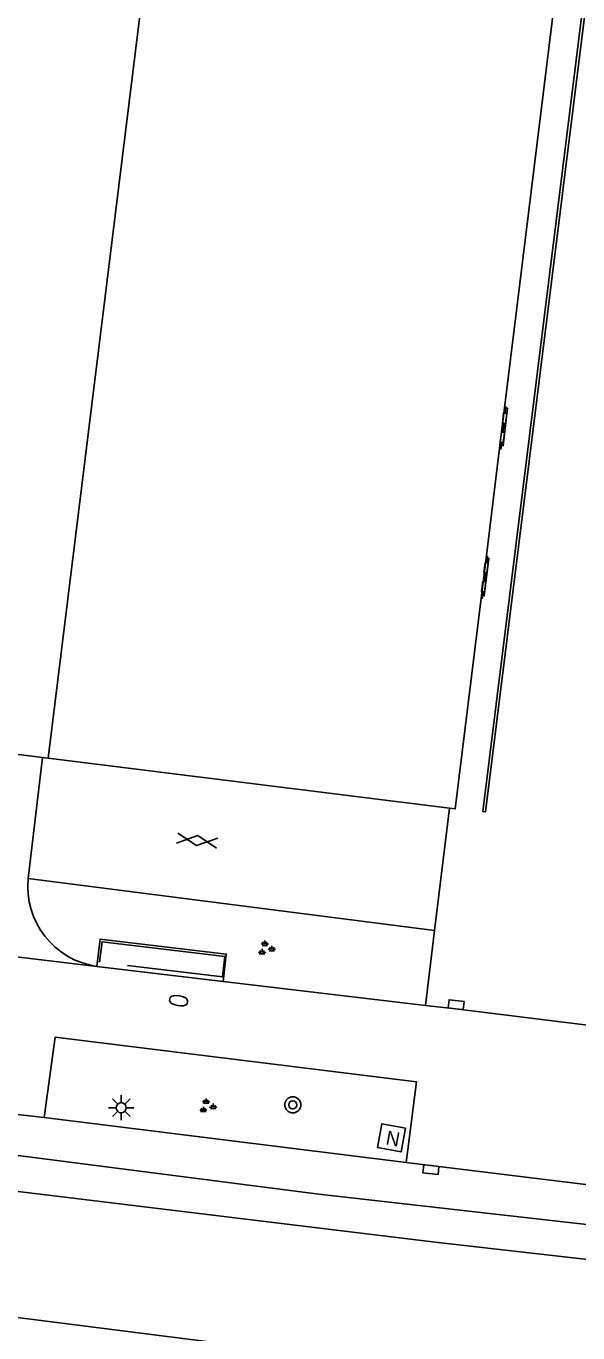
# Model space of a CAD drawing. Extents: x 131000 to 133014, y 396499 to 399001.
# Drawn here: x 131552 to 131579.4, y 397023 to 397087.7 of the extents above; entities that cross this region are included whole.
import ezdxf

# ---------------------------------------------------------------- set-up
doc = ezdxf.new("R2010")
doc.units = 0
for name, color, linetype in [('gg-afsc-hekwerk', 7, 'Continuous'), ('gg-bbg-hoofdgebouw', 7, 'Continuous'), ('gg-knt-verharding', 7, 'Continuous'), ('gg-knt-verharding nz', 7, 'Continuous'), ('gt-grn-afwateringsgoot', 7, 'Continuous'), ('gt-symb-afwateringsgoot', 7, 'Continuous'), ('gt-symb-boom', 7, 'Continuous'), ('gt-symb-brandkraan', 7, 'Continuous'), ('gt-symb-gesloten verharding', 7, 'Continuous'), ('gt-symb-groenvak', 7, 'Continuous'), ('gt-symb-kolk', 7, 'Continuous'), ('gt-symb-lichtmast', 7, 'Continuous'), ('gt-symb-nortonput', 7, 'Continuous')]:
    doc.layers.add(name, color=color, linetype=linetype)

# ---------------------------------------------------------------- blocks, each defined once
blk = doc.blocks.new('gt0-GESVH1')
at = {"layer": 'gt-symb-gesloten verharding'}
for p, q in [((-0.992, -0.261), (0.008, 0.239)), ((0.008, -0.261), (-0.992, 0.239)), ((0.008, 0.239), (1.008, -0.261)), ((1.008, 0.239), (0.008, -0.261))]:
    blk.add_line(p, q, dxfattribs=at)
blk = doc.blocks.new('gt0-BR')
at = {"layer": 'gt-symb-brandkraan'}
for centre, radius, start, end in [((-0.244, 0), 0.206, 107.56694, 252.43307), ((0.599, -2.664), 3, 106.89205, 107.56694), ((0, -0.691), 0.938, 73.10799, 106.89205), ((-0.599, -2.664), 3, 72.43309, 73.10799), ((0.244, 0), 0.206, 287.56695, 72.43309), ((0.599, 2.664), 3, 252.43307, 253.10797), ((0, 0.691), 0.938, 253.10797, 286.89206), ((-0.599, 2.664), 3, 286.89206, 287.56695)]:
    blk.add_arc(centre, radius, start, end, dxfattribs=at)
blk = doc.blocks.new('gt0-GRVAK')
at = {"layer": 'gt-symb-groenvak'}
for p, q in [((-0.11, 0.189), (-0.228, 0.24)), ((-0.182, 0.153), (0.088, 0.153)), ((-0.091, 0.211), (-0.156, 0.322)), ((-0.047, 0.214), (-0.047, 0.393)), ((-0.004, 0.211), (0.061, 0.322)), ((0.015, 0.189), (0.133, 0.24)), ((0.262, -0.052), (0.197, 0.059)), ((0.305, -0.049), (0.305, 0.13)), ((0.349, -0.052), (0.414, 0.059)), ((-0.245, -0.228), (-0.363, -0.177)), ((-0.318, -0.264), (-0.047, -0.264)), ((-0.226, -0.206), (-0.291, -0.095)), ((-0.183, -0.203), (-0.183, -0.024)), ((-0.139, -0.206), (-0.074, -0.095)), ((-0.12, -0.228), (-0.002, -0.177)), ((0.243, -0.074), (0.125, -0.023)), ((0.17, -0.11), (0.441, -0.11)), ((0.368, -0.074), (0.486, -0.023))]:
    blk.add_line(p, q, dxfattribs=at)
blk = doc.blocks.new('gt0-LMAST')
at = {"layer": 'gt-symb-lichtmast'}
for p, q in [((-0.182, 0.173), (-0.447, 0.438)), ((-0.005, 0.246), (-0.005, 0.621)), ((0.172, 0.173), (0.437, 0.438)), ((-0.255, -0.004), (-0.63, -0.004)), ((-0.182, -0.181), (-0.447, -0.446)), ((-0.005, -0.254), (-0.005, -0.629)), ((0.437, -0.446), (0.172, -0.181)), ((0.245, -0.004), (0.62, -0.004))]:
    blk.add_line(p, q, dxfattribs=at)
blk.add_circle((-0.005, -0.004), 0.25, dxfattribs=at)
blk = doc.blocks.new('gt0-BOOM')
at = {"layer": 'gt-symb-boom'}
for radius in [0.4, 0.2]:
    blk.add_circle((0, 0), radius, dxfattribs=at)
blk = doc.blocks.new('gt0-NPUT')
at = {"layer": 'gt-symb-nortonput'}
blk.add_lwpolyline([(-0.566, -0.608), (-0.566, 0.592), (0.634, 0.592), (0.634, -0.608)], close=True, dxfattribs=at)
blk.add_text('N', height=0.7, dxfattribs=at).set_placement((-0.221, -0.381))
blk = doc.blocks.new('gt0-AFWGT_1')
at = {"layer": 'gt-symb-afwateringsgoot'}
for p, q in [((-1.076, 0), (-0.726, 0)), ((-0.225, 0), (0.225, 0)), ((0.725, 0), (1.075, 0))]:
    blk.add_line(p, q, dxfattribs=at)
for points in [[(-0.726, 0.075), (-0.225, 0.075), (-0.225, -0.075), (-0.726, -0.075)], [(0.225, 0.075), (0.725, 0.075), (0.725, -0.075), (0.225, -0.075)]]:
    blk.add_lwpolyline(points, close=True, dxfattribs=at)
blk = doc.blocks.new('gt0-KOLK')
at = {"layer": 'gt-symb-kolk'}
blk.add_lwpolyline([(0, 0), (0.375, 0), (0.375, 0.4), (-0.375, 0.4), (-0.375, 0), (0, 0)], dxfattribs=at)

msp = doc.modelspace()

# ---------------------------------------------------------------- linework, layer by layer
at = {"layer": 'gg-afsc-hekwerk'}
msp.add_lwpolyline([(131555.696, 397041.331), (131555.816, 397042.343), (131561.914, 397041.62), (131561.793, 397040.607), (131557.076, 397041.167)], dxfattribs=at)
at = {"layer": 'gg-bbg-hoofdgebouw'}
for p, q in [((131561.421, 397118.541), (131553.14, 397051.44)), ((131575.788, 397068.814), (131578.302, 397089.226)), ((131575.558, 397066.948), (131575.788, 397068.814)), ((131574.871, 397061.367), (131575.558, 397066.948)), ((131574.641, 397059.505), (131574.871, 397061.367)), ((131553.14, 397051.44), (131573.05, 397048.976))]:
    msp.add_line(p, q, dxfattribs=at)
msp.add_lwpolyline([(131573.05, 397048.976), (131573.34, 397048.94), (131574.641, 397059.505)], dxfattribs=at)
at = {"layer": 'gg-knt-verharding'}
for p, q in [((131550.072, 397051.834), (131552.857, 397051.477)), ((131552.155, 397045.488), (131552.857, 397051.477)), ((131552.857, 397051.477), (131553.14, 397051.44)), ((131572.311, 397042.903), (131573.05, 397048.976)), ((131572.311, 397042.903), (131552.155, 397045.488)), ((131571.859, 397039.191), (131572.311, 397042.903)), ((131548.89, 397041.924), (131555.561, 397041.125)), ((131571.859, 397039.191), (131561.817, 397040.383)), ((131543.649, 397034.705), (131552.938, 397033.633)), ((131552.938, 397033.633), (131570.906, 397031.402)), ((131570.906, 397031.402), (131582.601, 397029.969))]:
    msp.add_line(p, q, dxfattribs=at)
for points in [[(131555.561, 397041.125), (131555.721, 397042.476), (131561.977, 397041.733), (131561.817, 397040.383)], [(131635.377, 397031.394), (131631.371, 397031.904), (131611.063, 397034.404), (131592.596, 397036.64), (131573.352, 397039.028), (131571.859, 397039.191)], [(131552.938, 397033.633), (131553.495, 397037.62), (131571.419, 397035.401), (131570.906, 397031.402)]]:
    msp.add_lwpolyline(points, dxfattribs=at)
msp.add_arc((131556.133, 397045.082), 3.999, 174.17861, 261.77654, dxfattribs=at)
at = {"layer": 'gg-knt-verharding nz'}
msp.add_line((131555.561, 397041.125), (131561.817, 397040.383), dxfattribs=at)
for points in [[(131604.316, 397027.828), (131600.385, 397027.163), (131588.04, 397027.402), (131566.563, 397029.84), (131532.856, 397034.168), (131505.057, 397037.526), (131490.467, 397039.333)], [(131490.265, 397037.49), (131541.57, 397031.181), (131572.347, 397027.447)], [(131489.416, 397031.593), (131571.435, 397021.213), (131579.311, 397019.142), (131583.199, 397017.669), (131587.053, 397015.65)], [(131572.347, 397027.447), (131586.896, 397025.808), (131597.116, 397025.203), (131601.579, 397025.347), (131604.803, 397025.981), (131608.626, 397027.558)]]:
    msp.add_lwpolyline(points, dxfattribs=at)
at = {"layer": 'gt-grn-afwateringsgoot'}
for points in [[(131584.177, 397136.919), (131585.582, 397136.746), (131587.68, 397153.392), (131587.78, 397153.38), (131581.926, 397105.734), (131574.844, 397048.782), (131574.713, 397048.798), (131583.302, 397118.004), (131581.87, 397118.188)], [(131575.558, 397066.948), (131575.708, 397066.931), (131575.925, 397068.798), (131575.788, 397068.814)], [(131574.641, 397059.505), (131574.774, 397059.488), (131575.007, 397061.35), (131574.871, 397061.367)]]:
    msp.add_lwpolyline(points, dxfattribs=at)

# ---------------------------------------------------------------- block references
at = {"layer": 'gt-symb-afwateringsgoot'}
for p, xscale, yscale, rotation in [((131575.731, 397067.82), 0.9999429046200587, 0.9999429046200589, 83.36715448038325), ((131574.811, 397060.418), 0.9999990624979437, 0.9999990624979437, -97.13745302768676)]:
    msp.add_blockref('gt0-AFWGT_1', p, dxfattribs=dict(at, xscale=xscale, yscale=yscale, rotation=rotation))
at = {"layer": 'gt-symb-boom'}
msp.add_blockref('gt0-BOOM', (131565.28, 397034.261), dxfattribs=at)
at = {"layer": 'gt-symb-brandkraan', "rotation": -9.556527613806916}
msp.add_blockref('gt0-BR', (131559.615, 397039.422), dxfattribs=at)
at = {"layer": 'gt-symb-gesloten verharding', "rotation": -7.295560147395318}
msp.add_blockref('gt0-GESVH1', (131560.528, 397047.371), dxfattribs=at)
at = {"layer": 'gt-symb-groenvak'}
for p in [(131563.936, 397042.014), (131561.025, 397034.19)]:
    msp.add_blockref('gt0-GRVAK', p, dxfattribs=at)
at = {"layer": 'gt-symb-kolk'}
for p, rotation in [((131573.352, 397039.028), -7.068140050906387), ((131572.158, 397031.247), 173.22321717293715)]:
    msp.add_blockref('gt0-KOLK', p, dxfattribs=dict(at, rotation=rotation))
at = {"layer": 'gt-symb-lichtmast'}
msp.add_blockref('gt0-LMAST', (131556.774, 397034.123), dxfattribs=at)
at = {"layer": 'gt-symb-nortonput', "rotation": -10.36632260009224}
msp.add_blockref('gt0-NPUT', (131570.14, 397032.639), dxfattribs=at)

doc.saveas('drawing.dxf')
